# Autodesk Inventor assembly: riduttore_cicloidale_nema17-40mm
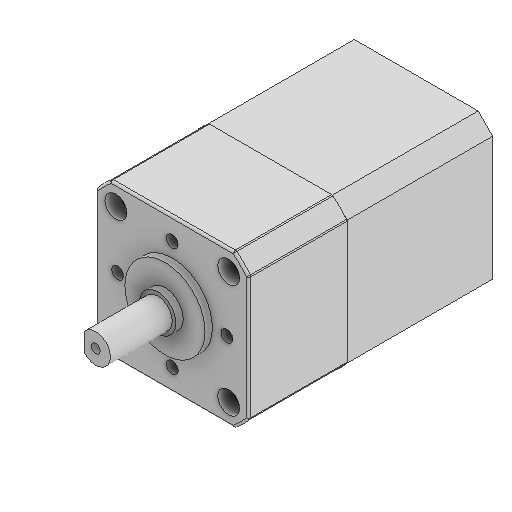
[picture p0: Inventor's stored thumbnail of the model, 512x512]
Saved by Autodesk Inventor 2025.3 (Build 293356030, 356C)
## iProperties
Created: 2026-03
Part Number: riduttore_cicloidale_nema17-40mm
Document SubType Name: Assembly
Designer: R5800u
Author: R5800u
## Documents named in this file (3)
- C:\Users\R5800u\Desktop\Riduttore cicloidale\riduttore_cicloidale_nema17-40mm.iam
- C:\Users\R5800u\Desktop\Riduttore cicloidale\NEMA 17-40mm.ipt
- C:\Users\R5800u\Desktop\Riduttore cicloidale\riduttore ciccloidale TS42 15-1.ipt
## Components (2 placed, 2 different names)
1. NEMA 17-40mm:1 — Coincidente:1, Coincidente:2, Angolo:1
2. riduttore ciccloidale TS42 15-1:1 — Coincidente:1, Coincidente:2, Angolo:1
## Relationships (3: Mate 2, Angle 1)
- Coincidente:1 [Mate]: NEMA 17-40mm:1 ↔ riduttore ciccloidale TS42 15-1:1
- Coincidente:2 [Mate]: NEMA 17-40mm:1 ↔ riduttore ciccloidale TS42 15-1:1
- Angolo:1 [Angle]: NEMA 17-40mm:1 ↔ riduttore ciccloidale TS42 15-1:1
